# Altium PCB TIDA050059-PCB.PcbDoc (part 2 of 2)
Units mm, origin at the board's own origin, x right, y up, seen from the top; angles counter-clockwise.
Board outline 100 x 120.38 mm, 2 copper layers (Top Layer, Bottom Layer), stack 1.575 mm thick; 126 components, 42 nets, 240 pads, 89 vias.
Unrouted connection lines stored in the file: 41.
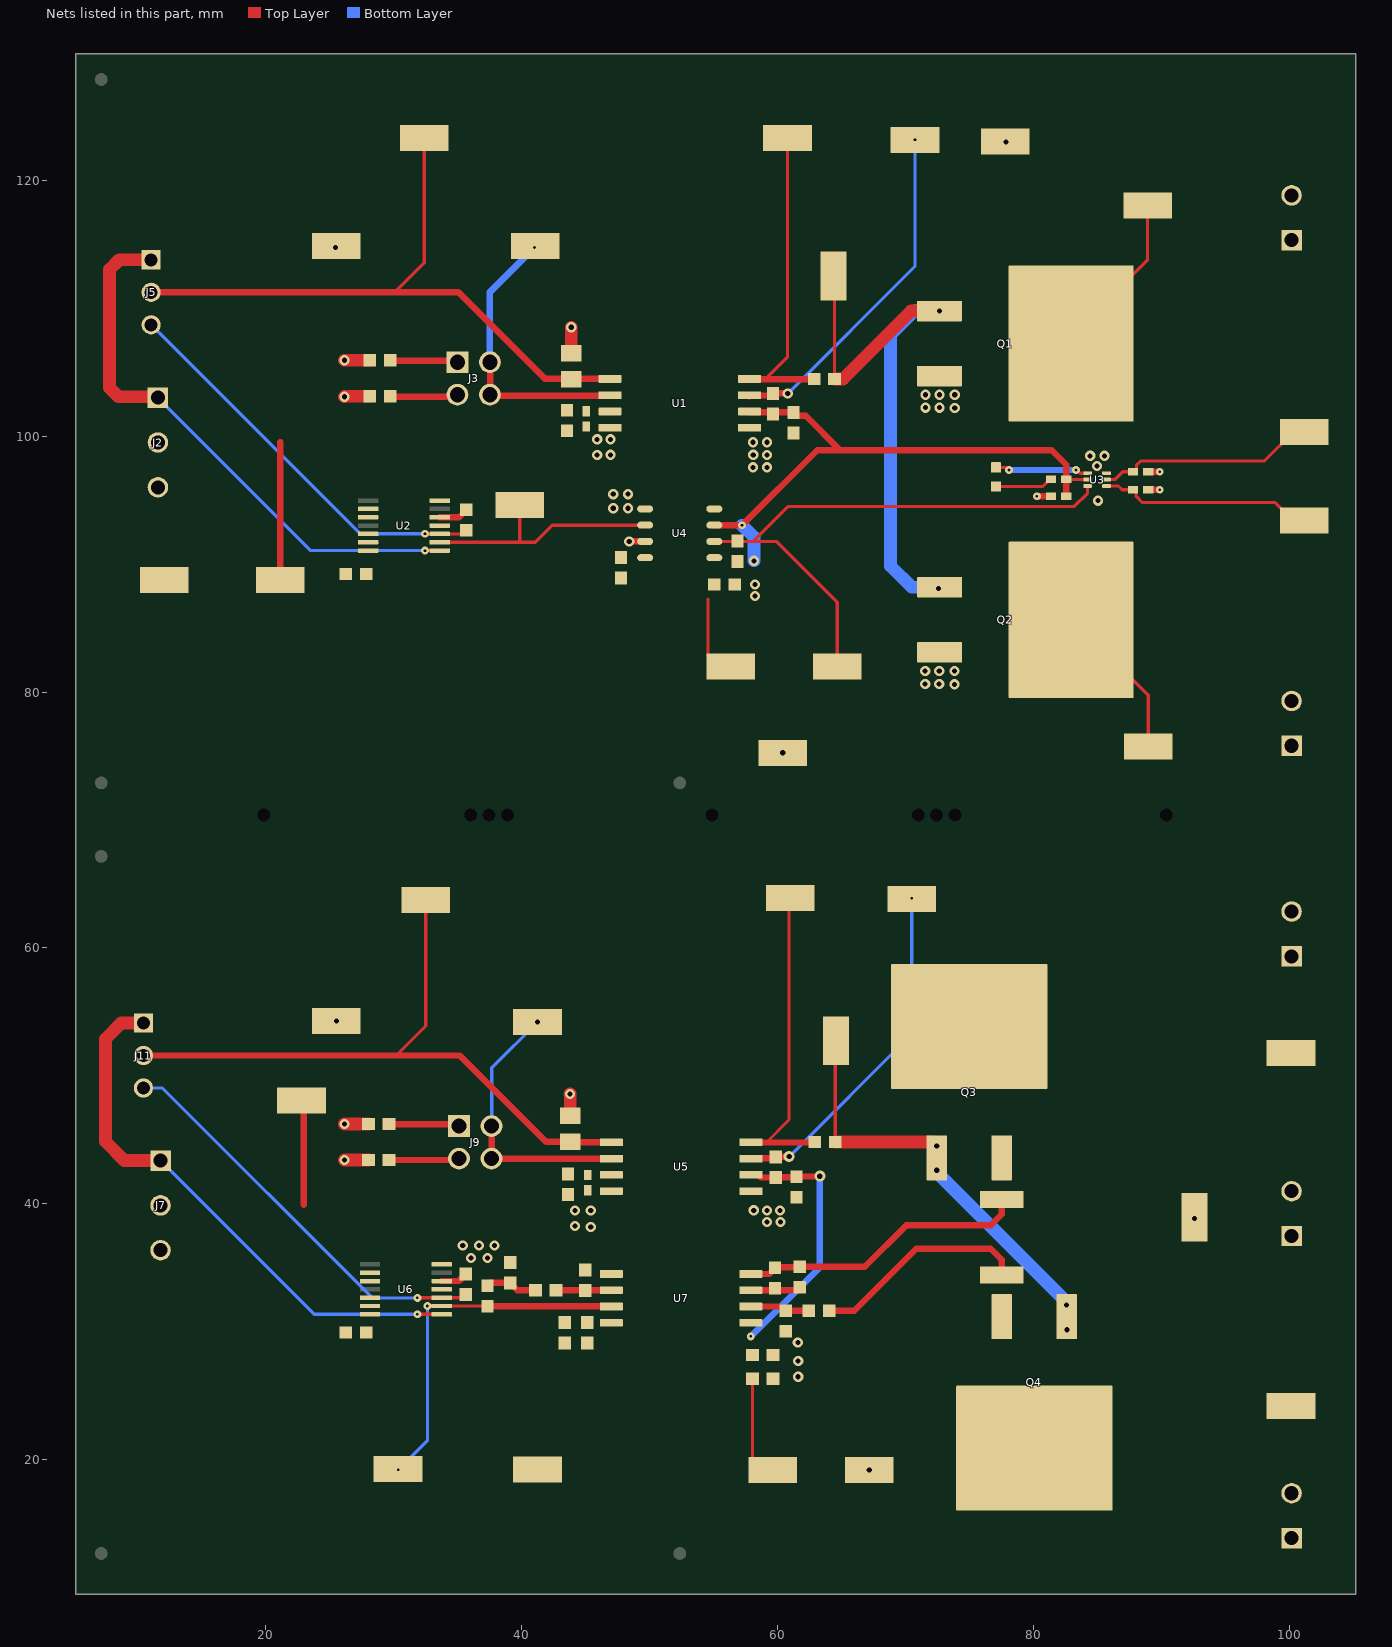
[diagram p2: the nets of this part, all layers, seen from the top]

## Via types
v1: diameter 0.8, hole 0.4, Top Layer to Bottom Layer, tented both sides, 70 vias
v2: diameter 0.61, hole 0.203, Top Layer to Bottom Layer, tented both sides, 16 vias
v3: diameter 0.864, hole 0.406, Top Layer to Bottom Layer, tented both sides, 3 vias

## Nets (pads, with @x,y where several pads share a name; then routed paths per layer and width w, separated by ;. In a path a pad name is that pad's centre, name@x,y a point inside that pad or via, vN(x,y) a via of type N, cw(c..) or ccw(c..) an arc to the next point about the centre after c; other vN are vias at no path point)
EN: C14.1 J11.2 TP22.1 U5.1 | length 52.5
  Top Layer w0.25: 30.245,51.599 32.55,53.904 TP22.1@32.55,63.75
  Top Layer w0.5: J11.2@10.5,51.6 30.245,51.599 35.216,51.599 41.953,44.862 43.895,44.862 43.922,44.835 47.03,44.835 U5.1@47.057,44.808
EN.: C5.1 J5.2 TP5.1 U1.1 | length 51.8
  Top Layer w0.25: 30.136,111.225 32.441,113.53 TP5.1@32.441,123.376
  Top Layer w0.5: J5.2@11.1,111.225 21.8,111.225 30.136,111.225 35.107,111.225 41.844,104.488 43.787,104.488 43.814,104.461 46.921,104.461 U1.1@46.948,104.434
IN: Q4.3 R10.1 R15.2 | length 17
  Top Layer w0.5: R15.2@64.075,31.655 66.03,31.655 70.875,36.5 76.7,36.5 77.56,35.64 R10.1@77.56,34.45
NetC20_1: C20.1 R15.1 U7.2 | length 4.7
  Top Layer w0.5: U7.2@57.95,31.993 60.218,31.993 60.556,31.655 C20.1@60.675,31.655 R15.1@62.475,31.655
NetC21_1: C21.1 R18.2 U7.3 | length 3.9
  Top Layer w0.5: U7.3@57.95,33.263 61.55,33.263 61.775,33.488 C21.1@61.775,33.5
NetC22_1: C22.1 R16.2 R17.1 | length 4.2
  Top Layer w0.5: R16.2@37.37,33.61 37.37,33.614 37.595,33.839 C22.1@39.157,33.839 39.157,33.814 39.708,33.263 R17.1@41.125,33.263 R17.1@41.224,33.363
NetD1_1: D1.1 U3.4 | length 7.3
  Top Layer w0.25: D1.1@77.1,97.55 77.823,97.55 78.026,97.348 v2(78.123,97.348) ; v2(83.355,97.348) 83.415,97.348 83.667,97.095 U3.4@84.26,97.095
  Bottom Layer w0.5: v2(78.123,97.348) v2(83.355,97.348)
NetD1_2: D1.2 R4.1 | length 4.5
  Top Layer w0.25: D1.2@77.1,96.05 80.74,96.05 81.3,96.61 R4.1@81.4,96.61
NetJ3_1: J3.1 R2.2 | length 5.4
  Top Layer w0.5: R2.2@29.734,105.871 34.833,105.871 J3.1@35.056,105.649
NetJ3_3: J3.3 R3.2 | length 5.4
  Top Layer w0.5: R3.2@29.734,103.021 29.778,103.065 35.012,103.065 J3.3@35.056,103.109
NetJ9_1: J9.1 R11.2 | length 5.4
  Top Layer w0.5: R11.2@29.842,46.245 34.942,46.245 J9.1@35.164,46.023
NetJ9_3: J9.3 R12.2 | length 5.4
  Top Layer w0.5: R12.2@29.842,43.395 29.886,43.439 35.12,43.439 J9.3@35.164,43.483
NetR6_1: R6.1 TP16.1 U3.6 U4.2 | length 44.8
  Top Layer w0.25: U4.2@55.098,91.765 58.145,91.765 ; TP16.1@64.7,82 64.7,87 59.935,91.765 58.145,91.765 ; U3.6@84.26,96.095 84.26,95.541 83.219,94.5 60.88,94.5 58.145,91.765
NetR7_2: R7.2 TP17.1 U3.1 | length 16.8
  Top Layer w0.25: U3.1@85.74,96.095 86.677,96.095 86.973,95.799 R7.2@87.8,95.799 87.874,95.799 88.049,95.624 88.049,95.298 88.553,94.794 98.921,94.794 100.315,93.4 TP17.1@101.2,93.4
NetR8_2: R8.2 TP14.1 U3.2 | length 17.2
  Top Layer w0.25: U3.2@85.74,96.595 86.385,96.595 87.005,97.215 R8.2@87.8,97.215 87.9,97.215 88.075,97.39 88.075,97.725 88.4,98.05 98.065,98.05 100.315,100.3 TP14.1@101.2,100.3
NetR14_1: R14.1 R17.2 U7.6 | length 4.3
  Top Layer w0.5: R17.2@42.725,33.263 42.75,33.263 U7.6@47.05,33.263
OC_Event: R16.1 TP31.1 U6.2 U7.7 | length 28.1
  Top Layer w0.25: v2(32.681,32.03) 33.95,32.03 37.35,32.03 R16.1@37.37,32.01 R16.1@37.378,32.002
  Top Layer w0.5: R16.1@37.378,32.002 47.041,32.002 U7.7@47.05,31.993
  Bottom Layer w0.25: v2(30.414,19.225) 32.681,21.492 v2(32.681,32.03)
OCP_EN: J11.3 R13.1 U6.3 | length 32.1
  Top Layer w0.25: v2(31.9,32.662) 31.909,32.671 U6.3@33.8,32.671 ; U6.3@33.8,32.68 35.43,32.68 R13.1@35.675,32.925
  Bottom Layer w0.25: J11.3@10.5,49.06 11.974,49.06 28.372,32.662 v2(31.9,32.662)
OT_Event: TP15.1 U2.2 U4.6 | length 19.4
  Top Layer w0.25: U2.2@33.8,91.7 39.896,91.7 ; TP15.1@39.896,94.607 39.896,91.7 ; U4.6@49.698,93.035 42.437,93.035 41.102,91.7 39.896,91.7
OTP_EN.: J5.3 R5.1 U2.3 | length 31.5
  Top Layer w0.25: v2(32.494,92.359) 32.499,92.354 33.65,92.354 33.654,92.35 35.436,92.35 R5.1@35.721,92.635
  Bottom Layer w0.25: J5.3@11.1,108.685 27.426,92.359 v2(32.494,92.359)
PXFR: J9.2 J9.4 TP24.1 U5.2 | length 21.6
  Top Layer w0.5: J9.2@37.712,46.018 37.712,43.478 37.761,43.527 47.041,43.527 U5.2@47.09,43.575
  Bottom Layer w0.25: J9.2@37.712,46.018 37.712,50.638 v3(41.286,54.211)
PXFR.: J3.2 J3.4 TP7.1 U1.2 | length 22.4
  Top Layer w0.5: J3.2@37.604,105.644 37.604,103.104 37.652,103.153 46.933,103.153 U1.2@46.981,103.201
  Bottom Layer w0.5: J3.2@37.57,105.77 37.57,111.251 v2(41.049,114.73)
SW1: J6.1 J6.2 Q3.4 TP19.1
SW1.: J1.1 J1.2 Q1.4 TP2.1 | length 13.9
  Top Layer w0.25: Q1.4@82.975,106.577 82.975,107.802 88.95,113.777 TP2.1@88.95,118
SW2: J10.1 J10.2 Q4.4 TP28.1
SW2.: J4.1 J4.2 Q2.4 TP9.1 | length 13.8
  Top Layer w0.25: Q2.4@82.975,87.009 82.975,85.784 89,79.759 TP9.1@89,75.75
USER_INPUT: J7.1 J11.1 U6.1 | length 43.5
  Top Layer w0.25: v2(31.9,31.38) U6.1@33.95,31.38
  Top Layer w1: J11.1@10.5,54.14 8.765,54.14 7.525,52.9 7.525,44.875 9.007,43.393 J7.1@11.836,43.393
  Bottom Layer w0.25: J7.1@11.836,43.393 23.849,31.38 v2(31.9,31.38)
USER_INPUT.: J2.1 J5.1 U2.1 | length 44
  Top Layer w0.25: v2(32.494,91.05) U2.1@33.8,91.05
  Top Layer w1: J5.1@11.1,113.765 8.615,113.765 7.85,113 7.85,103.765 8.55,103.065 11.558,103.065 J2.1@11.63,102.992
  Bottom Layer w0.25: J2.1@11.63,102.992 23.573,91.05 v2(32.494,91.05)
VDDH: C12.1 TP23.1 U5.7 | length 27.2
  Top Layer w0.5: U5.7@57.95,43.535 58,43.585 59.81,43.585 59.9,43.675 59.916,43.691 60.933,43.691 v3(60.949,43.707)
  Bottom Layer w0.25: v3(60.949,43.707) 70.525,53.283 v2(70.525,63.9)
VDDH.: C3.1 TP6.1 U1.7 | length 27.1
  Top Layer w0.5: U1.7@57.816,103.113 57.866,103.163 59.492,103.163 59.659,103.331 60.838,103.331 v1@60.84,103.333
  Bottom Layer w0.25: v1(60.84,103.313) 70.775,113.248 v2(70.775,123.142)
VDDM: C12.2 C13.1 C16.2 C19.2 TP25.1 U5.6 U7.1 | length 28.5
  Top Layer w0.25: C19.2@58.073,26.35 58.073,20.118 58.963,19.228 TP25.1@59.673,19.228
  Top Layer w0.5: U5.6@57.95,42.265 58.55,42.265 58.745,42.07 C12.2@59.9,42.07 59.93,42.1 61.495,42.1 C13.1@61.525,42.13 61.545,42.15 63.32,42.15 v3(63.34,42.17)
  Bottom Layer w0.5: v2(57.95,29.653) 63.341,35.045 v3@63.341,42.175
VDDM.: C3.2 C4.1 C8.2 C9.2 R4.2 R6.2 TP8.1 U1.6 U3.5 U4.1 U4.3 | length 52.5
  Top Layer w0.25: 54.6,87.25 54.6,82.89 55.49,82 TP8.1@56.375,82 ; R4.2@82.6,96.61 82.607,96.602 84.253,96.602 U3.5@84.26,96.595
  Top Layer w0.5: U4.3@55.098,93.035 v2(57.266,93.035) 63.131,98.9 64.925,98.9 ; U1.6@57.848,101.894 57.876,101.866 61.27,101.866 C4.1@61.298,101.838 61.298,101.813 61.523,101.588 62.237,101.588 64.925,98.9 ; C9.2@82.6,95.295 R4.2@82.6,96.61 82.6,97.765 81.465,98.9 64.925,98.9
  Bottom Layer w1: v2(57.266,93.035) 58.2,92.101 v1(58.2,90.249)
VDDP: C10.1 C11.1 C15.1 C17.1 C18.1 J7.2 R13.2 R14.2 TP18.1 U5.3 U6.4 U6.5 U6.9 U6.10 U6.12 U6.13 U6.14 U7.8 | length 10.3
  Top Layer w0.5: TP18.1@22.85,48.067 23.025,47.892 23.025,39.936 ; U6.5@33.8,33.98 35.155,33.98 35.675,34.5 R13.2@35.675,34.525
VDDP.: C1.1 C2.1 C6.1 C7.1 J2.2 R5.2 TP1.1 U1.3 U2.4 U2.5 U2.9 U2.10 U2.12 U2.13 U2.14 U4.8 | length 13.1
  Top Layer w0.5: TP1.1@21.2,88.75 21.2,99.535 ; U2.5@33.65,93.65 35.161,93.65 35.721,94.21 R5.2@35.721,94.235
VDRV: R9.1 TP20.1 U5.8 | length 25.1
  Top Layer w0.25: 59.174,44.805 60.931,46.562 60.931,63.806 TP20.1@61.025,63.9 ; 59.724,44.805 59.725,44.806
  Top Layer w0.5: U5.8@57.95,44.805 59.174,44.805 59.724,44.805 R9.1@63.2,44.805
VDRV.: R1.1 TP3.1 U1.8 | length 25.1
  Top Layer w0.25: 59.065,104.431 60.822,106.188 60.822,123.432 TP3.1@60.916,123.526 ; 59.615,104.431 59.616,104.433
  Top Layer w0.5: U1.8@57.841,104.431 59.065,104.431 59.615,104.431 R1.1@63.091,104.431
VGATE: Q3.1 Q4.1 R9.2 TP21.1 | length 34.6
  Top Layer w0.25: R9.2@64.55,44.85 64.55,52.695 TP21.1@64.614,52.759
  Top Layer w1: R9.2@64.55,44.85 72.18,44.85 72.48,44.55 v1(72.48,44.539)
  Bottom Layer w1: v1(72.48,44.539) 72.48,42.48 82.64,32.32 v1(82.64,30.178)
  other v1: 82.6,32.1 72.48,42.639
VGATE.: Q1.1 Q2.1 R1.2 TP4.1 | length 45.6
  Top Layer w0.25: TP4.1@64.413,112.5 64.5,112.413 R1.2@64.5,104.461
  Top Layer w1: R1.2@64.5,104.461 65.156,104.461 70.458,109.763 v1(72.7,109.763)
  Bottom Layer w1: v1(72.614,88.1) 72.534,88.18 70.541,88.18 68.875,89.846 68.875,107.9 70.738,109.763 v1(72.7,109.763)
VSSP: C10.2 C11.2 C14.2 C15.2 C17.2 C18.2 C22.2 J7.3 R11.1 R12.1 TP29.1 TP30.1 U5.4 U6.7 U7.5 | length 5.5
  Top Layer w1: v1(26.2,43.439) 28.064,43.439 R12.1@28.075,43.45 ; v1(26.2,46.256) 26.211,46.245 R11.1@28.075,46.245 ; v1(43.832,48.6) 43.85,48.582 C14.2@43.85,46.891
  other v1: 36.1,35.775 37.378,35.775 35.45,36.75 36.725,36.75 37.935,36.75 45.441,38.2 44.212,38.279 45.441,39.482 44.213,39.497 25.576,54.302
VSSP.: C1.2 C2.2 C5.2 C6.2 C7.2 J2.3 R2.1 R3.1 TP12.1 TP13.1 U1.4 U2.7 U4.5 U4.7 | length 7.3
  Top Layer w0.5: v1(48.45,91.765) U4.7@49.698,91.765
  Top Layer w1: v1(26.2,103.065) 26.239,103.104 R3.1@28.176,103.104 ; v1(26.2,105.915) R2.1@28.176,105.915 ; C5.2@43.922,106.456 v1(43.922,108.501)
  other v1: 47.2,94.355 48.349,94.355 47.2,95.457 48.351,95.457 45.948,98.519 46.981,98.53 45.948,99.738 46.981,99.738 25.5,114.73
VSSS: C13.2 C16.1 C19.1 C20.2 C21.2 J8.1 J8.2 Q3.3 R10.2 R18.1 TP26.1 TP27.1 U5.5 U7.4 | length 22.7
  Top Layer w0.5: U7.4@57.95,34.533 59.383,34.533 59.85,35 R18.1@59.85,35.025 59.888,35.063 61.738,35.063 C21.2@61.775,35.1 66.859,35.1 70.109,38.35 76.7,38.35 77.56,39.21 R10.2@77.56,40.35
  other v1: 67.2,19.227 61.65,26.5 61.65,27.726 61.624,29.177 59.209,38.599 60.263,38.601 92.6,38.876 58.177,39.504 59.209,39.497 60.234,39.497
VSSS.: C4.2 C8.1 C9.1 Q1.3 Q2.3 R7.1 R8.1 TP10.1 TP11.1 U1.5 U3.3 U4.4 | length 2.9
  Top Layer w0.5: v2(80.3,95.3) 80.302,95.298 81.398,95.298 C9.1@81.4,95.295 ; R7.1@89,95.799 89.002,95.797 89.898,95.797 v2(89.9,95.795) ; R8.1@89,97.215 v2(89.9,97.215)
  other v1: 60.45,75.25 73.857,80.601 71.571,80.62 72.664,80.62 71.571,81.634 72.671,81.634 73.857,81.634 58.28,87.5 58.28,88.4 85.075,94.95 58.123,97.55 59.206,97.55 85,97.664 84.463,98.45 85.575,98.45 58.145,98.53 59.206,98.519 58.123,99.515 59.206,99.515 73.887,102.194 71.6,102.213 72.693,102.213 71.6,103.227 72.7,103.227 73.887,103.227 77.89,122.959
pads on no net: FID1.1 FID2.1 FID3.1 FID4.1 FID5.1 FID6.1 SH-J1.0 SH-J2.0 SH-J3.0 SH-J4.0 U2.6 U2.8 U2.11 U6.6 U6.8 U6.11

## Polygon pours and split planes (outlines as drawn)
VDDP on Top Layer "TOP_LAYER_VDDP_P017" (solid, remove dead copper, pour order 17): 29.15,39.221 29.587,38.712 29.587,35.121 29.424,34.842 27.35,34.842 27.351,33.776 29.424,33.776 29.587,33.548 29.587,33.074 29.424,32.911 27.35,32.911 27.35,29 27.7,28.65 37.218,28.65 41.269,30.213 45.663,30.213 45.895,30.445 47.78,30.445 47.78,31.002 47.769,31.013 45.812,31.013 45.585,31.24 41.003,31.24 37.218,29.888 31.603,29.888 31.225,30.446 31.225,32.572 31.603,33.105 34.65,33.105 34.65,34.205 32.489,34.222 32.194,34.518 32.194,38.146 40.357,38.146 44.536,35.594 44.536,34.343 45.486,34.343 45.486,35.838 40.764,38.818 40.764,40.986 41.588,41.81 45.545,41.81 45.7,41.965 47.649,41.965 47.649,42.565 46.197,42.565 45.912,42.835 40.563,42.835 38.293,40.565 11.359,40.565 11.359,39.221
VSSS on Top Layer "TOP_LAYER_VSSS_P021" (solid, remove dead copper, pour order 21): 76.628,45.35 76.628,41.88 75.843,41.076 75.843,39.7 79.26,39.7 79.26,41 78.485,41.88 78.485,45.35
VSSS on Top Layer "TOP_LAYER_VSSS_P023" (solid, remove dead copper, pour order 23): 57.05,41.244 57.05,34.725 57.435,34.339 61.519,34.339 62.226,35.047 62.226,40.813 61.744,41.295 57.101,41.295
VDDM on Top Layer "TOP_LAYER_VDDM_P024" (solid, remove dead copper, pour order 24): 57.065,31.008 57.065,26.224 57.5,25.788 58.573,25.788 58.573,28.823 58.85,29.1 58.835,29.115 58.835,31.008
VSSS on Top Layer "TOP_LAYER_VSSS_P025" (solid, remove dead copper, pour order 25): 59.173,25.788 59.173,30.438 59.457,30.723 62.114,30.723 62.6,30.237 62.6,26.303 62.086,25.788
SW1 on Top Layer "TOP_LAYER_SW1_P026" (solid, remove dead copper, pour order 26): 68.969,58.794 68.969,49.331 69.291,49.009 101.072,49.009 102.2,50.039 102.2,63.186 101.14,64.416 91.459,64.416 85.943,58.9 69.164,58.9
SW2 on Top Layer "TOP_LAYER_SW2_P027" (solid, remove dead copper, pour order 27): 74.049,25.777 74.049,12.592 75.306,11.5 101.423,11.5 102.2,12.209 102.2,25.152 101.661,25.778
VSSP on Top Layer "TOP_LAYER_VSSP_P028" (solid, remove dead copper, pour order 28): 10.692,33.858 11.711,32.838 17.2,32.838 18.2,31.838 18.2,27.5 20.2,25.5 36.819,25.5 38.533,23.786 38.533,18.751 39.281,18.003 46.07,18.003 47.94,19.873 48.025,29.992 34.65,29.992 34.724,34.875 38.175,34.875 40.209,34.875 40.209,37.725 44.213,36.525 46.07,34.233 47.94,34.233 47.94,41.662 19.141,41.687 16.5,38.542 11.711,38.542 10.692,37.522
SW1. on Top Layer "TOP_LAYER_SW1._P046" (solid, remove dead copper, pour order 46): 78.123,113.9 78.123,101.123 88.3,101.123 89.848,102.671 89.848,105.388 96.86,112.4 100.8,112.4 101.4,113 101.4,119.4 100.6,120.2 87.3,120.2 86.235,119.6 86.235,115.4 85.335,114.5 78.946,114.5
VDDM. on Top Layer "TOP_LAYER_VDDM._P049" (solid, remove dead copper, pour order 49): 54.473,90.765 54.473,87.236 54.637,87.073 55.473,87.073 55.6,87.2 55.6,89.3 56,89.7 58.697,89.7 58.697,90.765
VSSS. on Top Layer "TOP_LAYER_VSSS._P050" (solid, remove dead copper, pour order 50): 56.198,88.875 56.175,88.852 56.175,87.2 56.302,87.073 58.979,87.073 59.207,87.301 59.207,88.7 59.032,88.875
VDDP. on Top Layer "TOP_LAYER_VDDP._P051" (solid, remove dead copper, pour order 51): 29.155,98.85 29.593,98.341 29.593,94.75 29.43,94.471 27.355,94.471 27.357,93.405 29.43,93.405 29.593,93.177 29.593,92.703 29.43,92.54 27.355,92.54 27.355,88.629 27.705,88.279 37.223,88.279 41.274,89.842 45.668,89.842 45.9,90.074 50.323,90.074 50.323,90.869 45.591,90.869 41.008,90.869 37.223,89.517 31.609,89.517 31.23,90.075 31.23,92.201 31.609,92.734 34.655,92.734 34.655,93.834 32.494,93.851 32.199,94.147 32.199,97.775 40.362,97.775 40.769,98.341 40.769,100.615 41.593,101.439 45.55,101.439 45.705,101.594 47.5,101.594 47.5,102.194 46.027,102.194 45.742,102.464 40.568,102.464 38.298,100.194 11.365,100.194 11.365,98.85
SW2. on Top Layer "TOP_LAYER_SW2._P053" (solid, remove dead copper, pour order 53): 78.09,91.8 78.09,74.445 79.26,73.275 101.2,73.275 102.2,74.275 102.2,81.5 101.2,82.5 95.827,82.5 89.919,88.408 89.919,90.181 88.3,91.8
VSSS. on Top Layer "TOP_LAYER_VSSS._P054" (solid, remove dead copper, pour order 54): 54.475,94.645 54.475,94.025 56.263,94.025 61.9,99.663 61.9,100.788 61.699,100.989 56.973,100.989 56.973,97.604 54.47,95.101 54.47,94.791
VSSS. on Top Layer "TOP_LAYER_VSSS._P055" (solid, remove dead copper, pour order 55): 70.95,105.435 70.964,105.421 70.964,101.936 71.5,101.4 73.887,101.4 74.45,101.963 74.45,105.435
VSSS. on Top Layer "TOP_LAYER_VSSS._P056" (solid, remove dead copper, pour order 56): 70.95,83.852 70.964,83.838 70.964,80.353 71.5,79.817 73.887,79.817 74.45,80.38 74.45,83.852
IN on Top Layer "TOP_LAYER_IN_P057" (solid, remove dead copper, pour order 57): 76.628,29.45 76.628,32.92 75.843,33.724 75.843,35.1 79.26,35.1 79.26,33.8 78.485,32.92 78.485,29.45
VSSS. on Top Layer "TOP_LAYER_VSSS._P059" (solid, remove dead copper, pour order 59): 86.085,96.945 86.385,97.245 86.385,98.45 85.86,98.975 83.85,98.975 83.7,98.825 83.705,98.82 83.705,98.05 84.05,98.05 84.875,97.225 84.875,95.6 84.175,94.9 84.175,94.625 84.384,94.416 86.056,94.416 86.385,94.745 85.485,95.645 85.419,95.645 85.3,95.764 85.3,96.945
VSSP. on Top Layer "TOP_LAYER_VSSP._P062" (solid, remove dead copper, pour order 62): 7.668,96.545 7.668,85.532 8.7,84.5 49.112,84.5 50.341,85.729 50.341,89.151 49.806,89.606 34.604,89.606 34.604,96.022 44.763,96.022 44.763,94.381 45.742,93.904 50.341,93.904 50.341,94.83 47.857,97.7 47.857,101.138 26.81,101.138 26.81,89.766 24.427,89.767 24.101,89.4 24.101,87.9 23.673,87.472 15.2,87.5 14.6,87.9 14.6,96.545 13.645,97.5 9.2,97.5
VSSS on Bottom Layer "BOTTOM_LAYER_VSSS_P014" (solid, remove dead copper, pour order 14): 57.075,15.504 58.825,13.754 79.059,13.754 100.846,35.541 100.846,42.054 76.806,66.094 59.665,66.094 57.075,63.504
VSSP on Bottom Layer "BOTTOM_LAYER_VSSP_P015" (solid, remove dead copper, pour order 15): 10.425,66.254 7.675,63.504 7.675,15.254 9.175,13.754 46.175,13.754 47.925,15.504 47.925,63.504 45.175,66.254
VSSS. on Bottom Layer "BOTTOM_LAYER_VSSS._P038" (solid, remove dead copper, pour order 38): 54.473,75.4 56.481,73.392 89.6,73.392 91,74.8 91,87.1 96.314,92.414 96.314,100.778 91,106.092 91,124.332 89.6,125.732 59.563,125.732 56.973,123.142 56.973,97.604 54.473,95.104
VSSP. on Bottom Layer "BOTTOM_LAYER_VSSP._P039" (solid, remove dead copper, pour order 39): 9.277,126.109 7.668,124.5 7.668,75.75 9.81,73.609 48.282,73.609 50.323,75.65 50.323,94.607 47.839,97.477 47.823,123.142 44.857,126.109

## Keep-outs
Keep-Out Layer:
  text ".Layer_Name" at 19.856,-12.306 h1.52

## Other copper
Top Layer:
  text ".Layer_Name" at 19.856,-12.306 h1.52
Bottom Layer:
  text ".Layer_Name" at 19.856,-12.306 h1.52

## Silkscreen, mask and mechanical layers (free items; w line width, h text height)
Top Overlay:
  lines w0.254: 24.791,86.456 25.791,85.456 60.194,85.456 61.194,86.456 61.194,96.031 60.194,97.031 25.791,97.031 24.791,96.031 24.791,86.456 ; 24.953,26.055 25.953,25.055 66.018,25.055 67.018,26.055 67.018,36.909 66.018,37.909 25.953,37.909 24.953,36.909 24.953,26.055 ; 40.776,99.096 41.776,98.096 64.828,98.096 65.828,99.096 65.828,108.315 64.828,109.315 41.776,109.315 40.776,108.315 40.776,99.096 ; 41.096,39.537 42.096,38.537 64.939,38.537 65.939,39.537 65.939,48.805 64.939,49.805 42.096,49.805 41.096,48.805 41.096,39.537 ; 75.376,94.314 76.376,93.314 91.744,93.314 92.744,94.314 92.744,98.985 91.744,99.985 76.376,99.985 75.376,98.985 75.376,94.314
  text "EN" at 31.7,125.333 h1.5
  text "VDRV" at 58.697,125.218 h1.5
  text "VDDH" at 68.87,125.1 h1.5
  text "VSSS" at 75.92,124.978 h1.5
  text "Max Loading Conditions: / V Load = 500Vdc/350Vrms / Frequency = 50/60Hz / I load = 4A" at 83.667,120.1 h0.9
  text "Recommended Conditions: / - Three Wire Mode: /      EN: 5-Vdc /      VDDP: 5-Vdc" at 10.648,120 h1.5
  text "SW1" at 83.466,117.418 h1.5
  text "VSSP" at 23.733,116.748 h1.5
  text "PXFR" at 39.221,116.73 h1.5
  text "SW1" at 92.971,116.418 h1.5
  text "VG" at 63.35,115.352 h1.5
  text "USER_INPUT" at 12.702,113.309 h1.5
  text "EN" at 12.702,110.85 h1.5
  text "Isolated Switch Driver" at 46.984,109.919 h1.5
  text "OTP_EN" at 12.702,108.109 h1.5
  text "PXFR #1" at 27.29,106.885 h1
  text "TPSI3050-Q1" at 48.751,106.249 h1.5
  text "CAUTION" at 92.299,105.218 h1.5
  text "PXFR #2" at 27.25,104.125 h1
  text "HOT SURFACE" at 90.099,103.918 h1.5
  text "USER_INPUT" at 16.117,102.571 h1.5
  text "SETB" at 99.2,102.218 h1.5
  text "VDDP" at 16.117,99.13 h1.5
  text "Temp Sense" at 93.4,96.316 h1.5
  text "LED ON / T > 60C" at 69.9,95.845 h1.5
  text "VSSP" at 16.117,95.653 h1.5
  text "OT_Event" at 37.152,91.931 h1.5
  text "VSSP" at 10.35,90.795 h1.5
  text "VDDP" at 19.4,90.664 h1.5
  text "SETA" at 99.352,90.662 h1.5
  text "DANGER" at 92.325,84.518 h1.5
  text "OUTA" at 62.755,83.918 h1.5
  text "VDDM" at 54.376,83.886 h1.5
  text "Over Temperature Detection" at 31.9,83.838 h1.5
  text "HIGH VOLTAGE" at 90.125,83.218 h1.5
  text "VSSS" at 58.627,77.218 h1.5
  text "SW2" at 93,76.918 h1.5
  text "SW2" at 83.466,75.268 h1.5
  text "VDRV" at 58.8,66.189 h1.5
  text "VDDH" at 68.3,66.189 h1.5
  text "EN" at 31.767,65.75 h1.5
  text "Max Loading Conditions: / V Load = 500Vdc/350Vrms / Frequency = 50/60Hz / I load = 4A" at 75.4,60.818 h0.9
  text "SW1" at 92.5,60.818 h1.5
  text "Recommended Conditions: / - Three Wire Mode: /      EN: 5-Vdc /      VDDP: 5-Vdc" at 10.246,59.8 h1.5
  text "VSSP" at 23.701,56.268 h1.5
  text "PXFR" at 39.558,56.25 h1.5
  text "VG" at 63.45,55.844 h1.5
  text "USER_INPUT" at 12.302,53.649 h1.5
  text "SW1" at 94,51.218 h1.5
  text "EN" at 12.302,51.191 h1.5
  text "Isolated Switch Driver" at 46.98,50.475 h1.5
  text "VDDP" at 21.276,50.067 h1.5
  text "OCP_EN" at 12.302,48.449 h1.5
  text "PXFR #1" at 27.231,47.336 h1
  text "TPSI3050-Q1" at 48.501,46.574 h1.5
  text "CAUTION" at 83.22,44.823 h1.5
  text "PXFR #2" at 27.231,44.516 h1
  text "HOT SURFACE" at 81.02,43.523 h1.5
  text "VSSS" at 98.3,43.318 h1.5
  text "USER_INPUT" at 16.117,42.711 h1.5
  text "VSSS" at 91.1,41.768 h1.5
  text "VDDP" at 16.117,39.27 h1.5
  text "Rsense" at 70.7,36.915 h1.5
  text "VSSP" at 16.117,35.793 h1.5
  text "DANGER" at 89.847,27.694 h1.5
  text "HIGH VOLTAGE" at 87.647,26.394 h1.5
  text "Over Current Detection" at 40.004,23.518 h1.5
  text "SW2" at 93.8,23.518 h1.5
  text "OC_Event" at 27.7,21.397 h1.5
  text "VDDM" at 57.463,21.344 h1.5
  text "VSSS" at 65.5,21.251 h1.5
  text "VSSP" at 39.57,21.132 h1.5
  text "SW2" at 92.8,15.018 h1.5
  text ".Layer_Name" at 19.856,-12.306 h1.52
Bottom Overlay:
  text ".Layer_Name" at 19.856,-12.306 h1.52
Top Paste:
  text ".Layer_Name" at 19.856,-12.306 h1.52
Bottom Paste:
  text ".Layer_Name" at 19.856,-12.306 h1.52
Top Solder:
  text ".Layer_Name" at 19.856,-12.306 h1.52
  text ".Layer_Name" at 19.856,-12.306 h1.52
Bottom Solder:
  text ".Layer_Name" at 19.856,-12.306 h1.52
Drill Guide:
  text ".Layer_Name" at 19.856,-12.306 h1.52
M1 Board Outline:
  the board outline again, w0.254
  text ".Layer_Name" at 19.856,-12.306 h1.52
M2 Board Dimensions:
  rectangle: 5.2,2.515 8.375,5.69
  rectangle: 8.375,-0.66 17.9,2.515
  lines w0.178: 5.2,2.515 30.6,2.515 ; 8.375,-0.66 8.375,5.69 ; 11.55,-0.66 11.55,5.69 ; 17.9,-0.66 17.9,5.69 ; 24.25,-0.66 24.25,5.69 ; 5.2,-0.66 30.6,-0.66 30.6,5.69 5.2,5.69 5.2,-0.66
  text ".Layer_Name" at 19.856,-12.306 h1.52
M3 3D STEP Top:
  text ".Layer_Name" at 19.856,-12.306 h1.52
M4 3D STEP Bottom:
  text ".Layer_Name" at 19.856,-12.306 h1.52
M5 Assembly Top:
  lines w0.254: -2.217,-14.126 165.423,-14.126 ; -2.217,-8.962 165.474,-8.962 ; -2.217,-3.797 -2.217,-19.291 99.51,-19.291 165.474,-19.291 165.474,-3.797 -2.204,-3.797 -2.204,-19.291 37.814,-19.291 ; 60.394,-19.291 60.394,-3.797 ; 92.576,-8.962 92.576,-3.797 ; 113.912,-8.962 113.912,-3.797 ; 129.711,-19.456 129.711,-14.304
  text "COMPONENTS MARKED 'DNP' SHOULD NOT BE POPULATED." at 34.499,1.41 h1.52
  text "ASSEMBLY VARIANT:" at 34.486,-1.524 h1.52
  text ".VariantName" at 60.801,-1.524 h1.52
  text "PCB VIEWED FROM TOP SIDE" at -0.604,-7.154 h1.52
  text "BOARD #:" at 62.299,-7.154 h1.52
  text ".PRJ_Number" at 76.155,-7.154 h1.52
  text "REV:" at 97.605,-7.154 h1.52
  text ".PCB_Rev" at 105.009,-7.154 h1.52
  text "SVN REV:" at 118.89,-7.154 h1.52
  text ".VersionControl_RevNumber" at 131.743,-7.154 h1.52
  text "TID #:" at 62.299,-12.319 h1.52
  text ".TID" at 76.155,-12.319 h1.52
  text "PLOT NAME =" at -0.604,-17.534 h1.52
  text ".plot_File_Name" at 19.856,-17.534 h1.52
  text "GENERATED    :" at 62.35,-17.534 h1.52
  text ".Print_Date" at 84.435,-17.534 h1.52
  text ".Print_Time" at 102.952,-17.534 h1.52
  text "TEXAS INSTRUMENTS" at 135.07,-17.534 h1.52
M6 Assembly Bottom:
  lines w0.254: -2.23,-8.974 165.461,-8.974 ; -2.179,-14.139 165.461,-14.139 ; 33.534,-19.469 33.534,-14.317 ; 49.332,-8.974 49.332,-3.81 ; 70.668,-8.974 70.668,-3.81 ; 102.85,-19.304 102.85,-3.81 ; 125.431,-19.304 165.449,-19.304 165.449,-3.81 -2.23,-3.81 -2.23,-19.304 63.734,-19.304 165.461,-19.304 165.461,-3.81
  text "COMPONENTS MARKED 'DNP' SHOULD NOT BE POPULATED." at 160.191,1.423 h1.52
  text ".VariantName" at 133.673,-1.524 h1.52
  text "ASSEMBLY VARIANT:" at 160.064,-1.524 h1.52
  text ".VersionControl_RevNumber" at 31.502,-7.167 h1.52
  text "SVN REV:" at 44.354,-7.167 h1.52
  text ".PCB_Rev" at 58.235,-7.167 h1.52
  text "REV:" at 65.639,-7.167 h1.52
  text ".PRJ_Number" at 87.09,-7.167 h1.52
  text "BOARD #:" at 100.945,-7.167 h1.52
  text "PCB VIEWED FROM BOTTOM SIDE" at 163.848,-7.167 h1.52
  text ".TID" at 87.09,-12.331 h1.52
  text "TID #:" at 100.945,-12.331 h1.52
  text "TEXAS INSTRUMENTS" at 28.174,-17.547 h1.52
  text ".Print_Time" at 60.293,-17.547 h1.52
  text ".Print_Date" at 78.809,-17.547 h1.52
  text "GENERATED    :" at 100.894,-17.547 h1.52
  text ".plot_File_Name" at 143.389,-17.547 h1.52
  text "PLOT NAME =" at 163.848,-17.547 h1.52
M9 Title Sheet:
  drawing of 57 lines, arcs and shapes, not listed
  text "1" at 23.992,213.627 h1.78
  text "2" at 87.382,213.627 h1.78
  text "3" at 150.611,213.627 h1.78
  text "4" at 214.28,213.627 h1.78
  text "5" at 277.755,213.627 h1.78
  text "6" at 341.382,213.627 h1.78
  text "A" at -5.379,184.595 h1.78
  text "A" at 370.541,184.595 h1.78
  text "B" at -5.379,124.143 h1.78
  text "B" at 370.541,124.143 h1.78
  text "C" at -5.379,63.818 h1.78
  text "C" at 370.541,63.818 h1.78
  text "PROJECT TITLE:" at 293.325,16.548 h1.14
  text ".PRJ_Title" at 294.595,13.162 h1.78
  text "DESIGNED FOR:" at 293.325,8.903 h1.14
  text ".PRJ_Customer" at 294.595,5.347 h1.78
  text "D" at -5.379,3.62 h1.78
  text "D" at 370.541,3.62 h1.78
  text "FILE NAME:" at 293.325,1.283 h1.14
  text ".PCB_File_Name_No_Path" at 294.595,-1.765 h1.78
  text "Texas Instruments (TI) and/or its licensors do not warrant the accuracy or completeness of this specification" at 167.1,-5.876 h1.14
  text "ENGINEER:" at 293.325,-6.083 h1.14
  text "LAYOUT BY:" at 331.552,-6.083 h1.14
  text "or any information contained therein. TI and/or its licensors do not warrant that this design will meet" at 165.957,-8.737 h1.14
  text ".PRJ_Engineer" at 294.595,-10.02 h1.78
  text ".PCB_Layout" at 332.835,-10.02 h1.78
  text "the specifications, will be suitable for your application or fit for any particular purpose, or will operate in" at 165.957,-11.599 h1.14
  text ".Layer_Name" at 19.856,-12.306 h1.52
  text "ALTIUM DESIGNER VERSION:" at 331.552,-13.957 h1.14
  text "an implementation. TI and/or its licensors do not warrant that the design is production worthy. You should" at 165.957,-14.461 h1.14
  text "completely validate and test your design implementation to confirm the system functionality for your application." at 167.1,-17.322 h1.14
  text ".print_Scale" at 294.595,-17.343 h1.78
  text ".Application_BuildNumber" at 332.835,-17.343 h1.78
  text "1" at 23.992,-22.593 h1.78
  text "2" at 87.382,-22.593 h1.78
  text "3" at 150.611,-22.593 h1.78
  text "4" at 214.28,-22.593 h1.78
  text "5" at 277.755,-22.593 h1.78
  text "6" at 341.382,-22.593 h1.78
M10 Fab Notes:
  drawing of 189 lines, arcs and shapes, not listed
  text "DESIGN INFORMATION" at 319.703,170.947 h1.52
  text "MIN. TRACK WIDTH:" at 303.331,167.591 h1.52
  text "8" at 331.176,167.591 h1.52
  text "MIL" at 335.107,167.591 h1.52
  text "7.874" at 326.95,164.5 h1.52
  text "MIN. CLEARANCE:" at 303.331,164.438 h1.52
  text "MIL" at 335.107,164.438 h1.52
  text "MIN. VIA PAD SIZE:" at 303.331,161.285 h1.52
  text "24" at 330.414,161.285 h1.52
  text "MIL" at 335.107,161.285 h1.52
  text "0.05mm (2MIL)" at 320.984,157.986 h1.52
  text "MINIMUM ANNULAR RING" at 294.969,157.777 h1.52
  text "EXTERNAL" at 338.968,157.777 h1.52
  text "PER" at 300.049,154.98 h1.52
  text "IPC-D-275 CLASS 2 LEVEL C" at 305.637,154.98 h1.52
  text "MIL, HOLES" at 343.438,152.428 h1.52
  text "+/-" at 333.47,152.209 h1.52
  text "+/-" at 355.161,152.209 h1.52
  text "REGISTRATION TOLERANCES:" at 294.969,152.182 h1.52
  text "METAL" at 325.443,152.182 h1.52
  text "5" at 340.079,152.183 h1.52
  text "3" at 361.237,152.183 h1.52
  text "MIL" at 364.19,152.182 h1.52
  text "HOLE SIZE TOLERANCE (UNLESS OTHERWISE SPECIFIED):" at 294.969,149.685 h1.52
  text "+/-" at 355.161,149.612 h1.52
  text "3" at 361.237,149.585 h1.52
  text "MIL" at 364.19,149.585 h1.52
  text "MATERIAL:" at 293.07,146.089 h1.52
  text "FR-4 High Tg" at 318.126,142.824 h1.52
  text "X" at 314.457,142.622 h1.52
  text "FR-408" at 303.763,142.507 h1.52
  text "OTHER" at 341.558,142.507 h1.52
  text "62 MIL (1.6mm) +/-10%" at 311.894,138.874 h1.52
  text "X" at 308.843,138.812 h1.52
  text "THICKNESS:" at 294.969,138.665 h1.52
  text "OTHER" at 344.53,138.665 h1.52
  text "TOLERANCE:" at 294.969,135.152 h1.52
  text "X" at 316.514,135.152 h1.52
  text "ANSI IPC-6012 TYPE 3 CLASS 2" at 321.036,135.152 h1.52
  text "OTHER +/-" at 321.035,131.489 h1.52
  text "BOW & TWIST:" at 294.969,127.802 h1.52
  text "X" at 316.514,127.802 h1.52
  text "ANSI IPC-6012 TYPE 3 CLASS 2" at 321.036,127.802 h1.52
  text "OTHER +/-" at 321.035,124.076 h1.52
  text "DRILLING:" at 293.07,120.758 h1.52
  text "NC_DRILL FILES" at 337.799,118.086 h1.52
  text "REFERENCE:" at 294.969,117.986 h1.52
  text "X" at 311.663,117.984 h1.52
  text "AS SHOWN" at 316.184,117.986 h1.52
  text "X" at 334.548,117.986 h1.52
  text "OTHER" at 345.368,114.373 h1.52
  text "PTH COPPER THICKNESS:" at 294.961,114.283 h1.52
  text "X" at 323.897,114.283 h1.52
  text "20-30 um" at 327.148,114.283 h1.52
  text "BOARD FINISH:" at 293.07,110.534 h1.52
  text "SILKSCREEN:" at 297.012,107.737 h1.52
  text "X" at 321.34,107.737 h1.52
  text "TOP" at 324.312,107.737 h1.52
  text "X" at 334.294,107.737 h1.52
  text "BOTTOM" at 337.291,107.737 h1.52
  text "SILKSCREEN COLOR:" at 297.012,103.795 h1.52
  text "X" at 321.315,103.795 h1.52
  text "WHITE" at 324.312,103.795 h1.52
  text "OTHER" at 337.291,103.795 h1.52
  text "X" at 324.642,100.152 h1.52
  text "GREEN" at 327.639,100.152 h1.52
  text "OTHER" at 343.336,100.152 h1.52
  text "SOLDER RESIST COLOR:" at 297.012,99.977 h1.52
  text "X" at 324.642,96.234 h1.52
  text "MATTE" at 327.639,96.234 h1.52
  text "SEMI-GLOSS" at 343.325,96.217 h1.52
  text "IMMERSION GOLD (ENIG)" at 320.019,91.845 h1.52
  text "ENEPIG" at 353.993,91.662 h1.52
  text "SURFACE FINISH:" at 293.07,91.636 h1.52
  text "X" at 315.498,91.636 h1.52
  text "IMM. TIN/SILVER OR EQUIV" at 301.44,88.149 h1.52
  text "OTHER" at 337.799,88.049 h1.52
  text "ARRAY/PANEL:" at 293.07,84.102 h1.52
  text "CUT AND TRIM PER M1 BOARD OUTLINE" at 320.019,83.893 h1.52
  text "N.C. ROUTE" at 320.019,80.44 h1.52
  text "X" at 337.495,80.44 h1.52
  text "V. SCORE" at 342.016,80.44 h1.52
  text "CERTIFICATION:" at 293.07,77.16 h1.52
  text "MATERIALS AND WORKMANSHIP FOR ALL PCBS" at 311.485,77.16 h1.52
  text "TO MEET OR EXCEED THE REQUIREMENTS OF:" at 311.485,74.771 h1.52
  text "X" at 302.278,71.503 h1.52
  text "ANSI IPC-A-600F CLASS ->" at 305.529,71.503 h1.52
  text "X" at 347.388,71.503 h1.52
  text "2" at 350.182,71.503 h1.52
  text "1" at 342.181,71.465 h1.52
  text "3" at 359.173,71.465 h1.52
  text "X" at 322.902,67.752 h1.52
  text "RoHS" at 326.153,67.752 h1.52
  text "OTHER" at 342.521,67.752 h1.52
  text "PER ORDER" at 352.607,67.752 h1.52
  text "ALL BOARDS MUST MEET OR EXCEED UL94-V0 REQUIREMENTS." at 293.769,63.845 h1.52
  text "PCB MUST BEAR THE UL94V-0 UL REGISTERED MATERIAL ID NUMBER" at 293.769,60.897 h1.52
  text "ADDITIONAL REQUIREMENTS:" at 293.07,56.594 h1.52
  text "MICROSECTION:" at 294.969,53.873 h1.52
  text "YES" at 317.975,53.873 h1.52
  text "REQUIRED" at 339.857,50.207 h1.52
  text "BARE BOARD ELEC. TEST:" at 294.969,50.134 h1.52
  text "NONE" at 328.135,50.134 h1.52
  text "X" at 336.86,50.134 h1.52
  text "PER ORDER" at 354.893,50.134 h1.52
  text "XX MIL VIAS REQUIRE NON-CONDUCTIVE FILL AND PLANARIZE" at 299.24,44.928 h1.5
  text "XX MIL VIAS REQUIRE CONDUCTIVE FILL AND PLANARIZE" at 299.443,42.287 h1.52
  text "OUTER XX MIL TRACES REQUIRE 50 OHM SINGLE-ENDED IMPEDANCE" at 299.418,38.137 h1.47
  text "LAYER 2 & 3 (INNER LAYERS) XX MIL WIDE, XX MIL SPACE / TRACES REQUIRE 100 OHM DIFFERENTIAL IMPEDANCE" at 299.215,32.15 h1.52
  text ".Layer_Name" at 19.856,-12.306 h1.52
M11 Gerber Information:
  lines w0.254: -2.217,-14.126 165.423,-14.126 ; -2.217,-8.962 165.474,-8.962 ; -2.217,-3.797 -2.217,-19.291 99.51,-19.291 165.474,-19.291 165.474,-3.797 -2.204,-3.797 -2.204,-19.291 37.814,-19.291 ; 60.394,-19.291 60.394,-3.797 ; 92.576,-8.962 92.576,-3.797 ; 113.912,-8.962 113.912,-3.797 ; 129.711,-19.456 129.711,-14.304
  text "ALL ARTWORK VIEWED FROM TOP SIDE" at -0.604,-7.154 h1.52
  text "BOARD #:" at 62.299,-7.154 h1.52
  text ".PRJ_Number" at 76.155,-7.154 h1.52
  text "REV:" at 97.605,-7.154 h1.52
  text ".PCB_Rev" at 105.009,-7.154 h1.52
  text "SVN REV:" at 118.89,-7.154 h1.52
  text ".VersionControl_RevNumber" at 131.743,-7.154 h1.52
  text "LAYER NAME =" at -0.604,-12.306 h1.52
  text "TID #:" at 62.299,-12.319 h1.52
  text ".TID" at 76.155,-12.319 h1.52
  text "PLOT NAME =" at -0.604,-17.534 h1.52
  text ".plot_File_Name" at 19.856,-17.534 h1.52
  text "GENERATED    :" at 62.35,-17.534 h1.52
  text ".Print_Date" at 84.435,-17.534 h1.52
  text ".Print_Time" at 102.952,-17.534 h1.52
  text "TEXAS INSTRUMENTS" at 135.07,-17.534 h1.52
M12 Stackup:
  drawing of 191 lines, arcs and shapes, not listed
  text "Layer" at 254.669,209.523 h1.52
  text "Name" at 265.08,209.523 h1.52
  text "Material" at 288.696,209.523 h1.52
  text "Thickness" at 310.534,209.523 h1.52
  text "Constant" at 327.04,209.523 h1.52
  text "Board Layer Stack" at 341.514,209.523 h1.52
  text "Top Overlay" at 265.08,206.475 h1.52
  text "Top Solder" at 265.08,203.427 h1.52
  text "Solder Resist" at 288.696,203.427 h1.52
  text "0.40mil" at 310.534,203.427 h1.52
  text "3.5" at 327.04,203.427 h1.52
  text "1" at 254.669,200.379 h1.52
  text "Top Layer" at 265.08,200.379 h1.52
  text "1.40mil" at 310.534,200.379 h1.52
  text "Dielectric1" at 265.08,197.331 h1.52
  text "FR-4 High Tg" at 288.696,197.331 h1.52
  text "59.20mil" at 310.534,197.331 h1.52
  text "4.8" at 327.04,197.331 h1.52
  text "2" at 254.669,194.283 h1.52
  text "Bottom Layer" at 265.08,194.283 h1.52
  text "1.40mil" at 310.534,194.283 h1.52
  text "Bottom Solder" at 265.08,191.235 h1.52
  text "Solder Resist" at 288.696,191.235 h1.52
  text "0.40mil" at 310.534,191.235 h1.52
  text "3.5" at 327.04,191.235 h1.52
  text "Bottom Overlay" at 265.08,188.187 h1.52
  text ".Layer_Name" at 19.856,-12.306 h1.52
M13 Component Bodies Top:
  text ".Layer_Name" at 19.856,-12.306 h1.52
M14 Component Bodies Bottom:
  text ".Layer_Name" at 19.856,-12.306 h1.52
M15 Courtyards Top:
  text ".Layer_Name" at 19.856,-12.306 h1.52
M16 Courtyards Bottom:
  text ".Layer_Name" at 19.856,-12.306 h1.52
Drill Drawing:
  circle w0.254: c152.256,147.138 r0.702
  lines w0.254: 151.554,122.578 152.958,122.578 152.256,121.174 151.554,122.578 ; 151.554,124.332 152.256,124.683 152.958,124.332 152.607,125.034 152.958,125.736 152.256,125.385 151.554,125.736 151.905,125.034 151.554,124.332 ; 151.554,127.841 151.905,127.841 151.905,127.49 152.607,127.49 152.607,127.841 152.958,127.841 152.958,128.542 152.607,128.542 152.607,128.893 151.905,128.893 151.905,128.542 151.554,128.542 151.554,127.841 ; 151.554,130.648 152.256,130.998 152.958,130.648 152.607,131.349 152.958,132.051 152.256,131.7 151.554,132.051 151.905,131.349 151.554,130.648 ; 151.554,133.805 152.958,133.805 152.958,135.209 151.554,135.209 151.554,133.805 ; 151.554,138.366 152.958,138.366 152.256,136.963 151.554,138.366 ; 151.554,140.121 151.554,140.472 151.905,140.822 151.554,141.173 151.554,141.524 151.905,141.524 152.256,141.173 152.607,141.524 152.958,141.524 152.958,141.173 152.607,140.822 152.958,140.472 152.958,140.121 152.607,140.121 152.256,140.472 151.905,140.121 151.554,140.121 ; 151.554,143.98 152.256,143.278 152.958,143.98 152.256,144.682 151.554,143.98 ; 151.835,122.297 152.677,122.297 152.256,121.455 151.835,122.297 ; 151.835,124.613 152.256,124.823 152.677,124.613 152.466,125.034 152.677,125.455 152.256,125.244 151.835,125.455 152.045,125.034 151.835,124.613 ; 151.835,127.981 152.045,127.981 152.045,127.771 152.466,127.771 152.466,127.981 152.677,127.981 152.677,128.402 152.466,128.402 152.466,128.613 152.045,128.613 152.045,128.402 151.835,128.402 151.835,127.981
  lines w0.305: 150.282,120.227 232.362,120.227 ; 150.282,148.647 232.362,148.647 ; 158.864,117.069 158.864,151.804 ; 167.296,117.069 167.296,151.804 ; 183.465,117.069 183.465,151.804 ; 190.047,117.069 190.047,151.804 ; 199.576,117.069 199.576,151.804 ; 217.974,117.069 217.974,151.804 ; 150.282,117.069 232.362,117.069 232.362,151.804 150.282,151.804 150.282,117.069
  text "Symbol" at 152.177,149.594 h1.83
  text "Quantity" at 159.811,149.594 h1.83
  text "Finished Hole Size" at 168.244,149.594 h1.83
  text "Plated" at 184.412,149.594 h1.83
  text "Hole Type" at 190.995,149.594 h1.83
  text "Drill Layer Pair" at 200.524,149.594 h1.83
  text "Hole Tolerance" at 218.922,149.594 h1.83
  text "16" at 159.811,146.436 h1.52
  text "8.00mil (0.203mm)" at 168.244,146.436 h1.52
  text "PTH" at 184.412,146.436 h1.52
  text "Round" at 190.995,146.436 h1.52
  text "Top Layer - Bottom Layer" at 200.524,146.436 h1.52
  text "70" at 159.811,143.278 h1.52
  text "15.75mil (0.400mm)" at 168.244,143.278 h1.52
  text "PTH" at 184.412,143.278 h1.52
  text "Round" at 190.995,143.278 h1.52
  text "Top Layer - Bottom Layer" at 200.524,143.278 h1.52
  text "3" at 159.811,140.121 h1.52
  text "16.00mil (0.406mm)" at 168.244,140.121 h1.52
  text "PTH" at 184.412,140.121 h1.52
  text "Round" at 190.995,140.121 h1.52
  text "Top Layer - Bottom Layer" at 200.524,140.121 h1.52
  text "6" at 159.811,136.963 h1.52
  text "40.00mil (1.016mm)" at 168.244,136.963 h1.52
  text "PTH" at 184.412,136.963 h1.52
  text "Round" at 190.995,136.963 h1.52
  text "Top Layer - Bottom Layer" at 200.524,136.963 h1.52
  text "16" at 159.811,133.805 h1.52
  text "43.31mil (1.100mm)" at 168.244,133.805 h1.52
  text "PTH" at 184.412,133.805 h1.52
  text "Round" at 190.995,133.805 h1.52
  text "Top Layer - Bottom Layer" at 200.524,133.805 h1.52
  text "8" at 159.811,130.648 h1.52
  text "47.24mil (1.200mm)" at 168.244,130.648 h1.52
  text "PTH" at 184.412,130.648 h1.52
  text "Round" at 190.995,130.648 h1.52
  text "Top Layer - Bottom Layer" at 200.524,130.648 h1.52
  text "6" at 159.811,127.49 h1.52
  text "39.37mil (1.000mm)" at 168.244,127.49 h1.52
  text "NPTH" at 184.412,127.49 h1.52
  text "Slot" at 190.995,127.49 h1.52
  text "Top Layer - Bottom Layer" at 200.524,127.49 h1.52
  text "2" at 159.811,124.332 h1.52
  text "39.37mil (1.000mm)" at 168.244,124.332 h1.52
  text "NPTH" at 184.412,124.332 h1.52
  text "Slot" at 190.995,124.332 h1.52
  text "Top Layer - Bottom Layer" at 200.524,124.332 h1.52
  text "1" at 159.811,121.174 h1.52
  text "39.37mil (1.000mm)" at 168.244,121.174 h1.52
  text "NPTH" at 184.412,121.174 h1.52
  text "Slot" at 190.995,121.174 h1.52
  text "Top Layer - Bottom Layer" at 200.524,121.174 h1.52
  text "128 Total" at 159.811,118.017 h1.52
  text "Slot definitions :" at 152.177,115.806 h1.52
  text "Routed Path Length" at 163.625,115.806 h1.52
  text "= Calculated from tool start centre position to tool end centre position." at 177.334,115.806 h1.52
  text "Hole Length" at 163.625,114.543 h1.52
  text "= Routed Path Length + Tool Size = Slot length as defined in the PCB layout" at 172.259,114.543 h1.52
  text ".Layer_Name" at 19.856,-12.306 h1.52
M17 Embedded Cavity:
  text ".Layer_Name" at 19.856,-12.306 h1.52
M18 Embedded Assembly:
  text ".Layer_Name" at 19.856,-12.306 h1.52
M19 Embedded Keepout:
  text ".Layer_Name" at 19.856,-12.306 h1.52

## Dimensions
5.2,-0.66 to 30.6,-0.66 on M2 Board Dimensions
5.2,9.5 to 5.2,129.875 on M2 Board Dimensions
5.2,9.5 to 105.2,9.5 on M2 Board Dimensions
